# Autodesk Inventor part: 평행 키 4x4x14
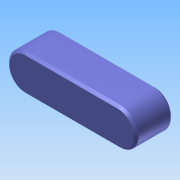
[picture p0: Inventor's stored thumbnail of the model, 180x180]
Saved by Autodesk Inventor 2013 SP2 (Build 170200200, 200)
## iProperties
Created: 2026-07
Part Number: 평행 키 4x4x14
Material: Generic
Document SubType Name: Modeling
Designer: a
Density: 1 g/cm^3
Author: a
변환 표준: STEP AP214IS
전처리기: Build: 200, Release: 2013 SP2 Update 6 - Date: Thu 07/17/2014
전송 단위: 밀리미터
불확실성: 0.01
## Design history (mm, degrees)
node "평행 키 4x4x141"
node "솔리드1"
node "기준1"
